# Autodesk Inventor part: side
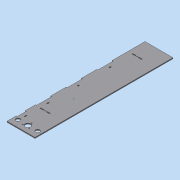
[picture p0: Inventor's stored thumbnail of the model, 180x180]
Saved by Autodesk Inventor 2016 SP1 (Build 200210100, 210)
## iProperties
Created: 2016-06
Part Number: side
Material: Generic
Document SubType Name: Modeling
Designer: Mohamed A.
Density: 1 g/cm^3
Appearance: Default
d0: 85.000 mm
d1: 320.000 mm
d2: 3.000 mm
d3: 0.00 deg
d6: 3.000 mm
d4: 233.000 mm
Author: Mohamed A.
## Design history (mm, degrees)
sketch "Sketch1"
  geometry: L1 (-42.5, 160)-(42.5, 160); L2 (42.5, 160)-(42.5, -160); L3 (42.5, -160)-(-42.5, -160); L4 (-42.5, -160)-(-42.5, 160); L5 (-42.5, 160)-(42.5, -160); L6 (42.5, 160)-(-42.5, -160); 1 further point
  constraints: 12 end point, 2 midpoint, 2 parallel, 1 horizontal, 1 perpendicular
  dimensions: "d0" = 85 distance of L2.end L3.end; "d1" = 320 distance of L1.end L2.end
extrude "Extrusion1" new body sketch "Sketch1" distance "d2" = 3; taper "d3" = 0 deg
sketch "Sketch2"
  geometry: L1 (-26.505, -73)-(-16.505, -73) reference; L2 (-7.505, -76)-(2.495, -76) reference; L3 (42.5, 160)-(-42.5, 160) reference; L4 (-42.5, 113.4)-(-39.5, 113.4); L5 (-39.5, 113.4)-(-39.5, 160); L6 (-42.5, 66.8)-(-39.5, 66.8); L7 (-39.5, 66.8)-(-39.5, 20.2); L8 (-39.5, 20.2)-(-42.5, 20.2); L9 (-39.5, -26.4)-(-42.5, -26.4); L10 (-42.5, -26.4)-(-42.5, -73); L11 (-39.5, 160)-(-42.5, 160); L12 (-42.5, 113.4)-(-42.5, 160); L13 (-42.5, 66.8)-(-42.5, 20.2); L14 (-39.5, -26.4)-(-39.5, -73); L15 (-42.5, -73)-(-39.5, -73); L16 (-42.5, -104)-(-39.5, -104); L17 (-39.5, -104)-(-39.5, -132); L18 (-39.5, -132)-(-42.5, -132); L19 (-42.5, -132)-(-42.5, -104); L20 (-42.5, -160)-(42.5, -160) reference; 1 further point; 1 other entity
  constraints: 32 end point, 6 perpendicular, 5 horizontal, 3 parallel, 2 point on line, 2 vertical, 1 collinear, 2 other
  dimensions: "d4" = 233 distance from line of L3 L1.start (derived); "d6" = 3 distance of L4.start L4.end; "d7" = 46.6 distance between parallel lines of L3 L4 (= 0.2 x d4); "d8" = 3 distance of L6.start L6.end; "d9" = 46.6 distance between parallel lines of L4 L6 (= d7); "d10" = 46.6 distance between parallel lines of L6 L8 (= d7); "d11" = 46.6 distance between parallel lines of L9 L8 (= d10); "d16" = 3 distance of L17.end L18.end; "d17" = 28 distance between parallel lines of L18 L16 (= 0.333333 x d18); "d18" = 84 distance between parallel lines of L20 L2 (derived); "d19" = 28 distance between parallel lines of L16 L2 (= d17); "d20" = 3 distance between parallel lines of L10 L14
extrude "Extrusion2" cut sketch "Sketch2" distance "d12" = 10; taper "d13" = 0 deg
sketch "Sketch3"
  geometry: L1 (-29.5, 142.2)-(-26.5, 142.2); L2 (-26.5, 142.2)-(-26.5, 136.2); L3 (-26.5, 136.2)-(-29.5, 136.2); L4 (-29.5, 136.2)-(-29.5, 142.2); L5 (-29.5, 45.05)-(-26.5, 45.05); L6 (-26.5, 45.05)-(-26.5, 40.5); L7 (-26.5, 40.5)-(-29.5, 40.5); L8 (-29.5, 40.5)-(-29.5, 45.05); L9 (-29.5, -46.7)-(-26.5, -46.7); L10 (-26.5, -46.7)-(-26.5, -52.7); L11 (-26.5, -52.7)-(-29.5, -52.7); L12 (-29.5, -52.7)-(-29.5, -46.7); L13 (-29.5, -115)-(-26.5, -115); L14 (-26.5, -115)-(-26.5, -121); L15 (-26.5, -121)-(-29.5, -121); L16 (-29.5, -121)-(-29.5, -115); L17 (-10.455, 130)-(-13.555, 130) reference; L18 (-10.455, 130)-(-10.455, 127) reference; L19 (-13.555, 127)-(-10.455, 127) reference; L20 (-13.555, 130)-(-13.555, 127) reference; L21 (-10.455, -73)-(-13.555, -73) reference; L22 (-10.455, -73)-(-10.455, -76) reference; L23 (-13.555, -76)-(-10.455, -76) reference; L24 (-13.555, -73)-(-13.555, -76) reference; L25 (-16.505, 130)-(-16.505, 127) reference; L26 (-16.505, 127)-(-26.505, 127) reference; L27 (-26.505, 127)-(-26.505, 130) reference; L28 (-26.505, 130)-(-16.505, 130) reference; L29 (-7.505, 127)-(-7.505, 130) reference; L30 (-7.505, 130)-(2.495, 130) reference; L31 (2.495, 130)-(2.495, 127) reference; L32 (2.495, 127)-(-7.505, 127) reference; L33 (2.495, -73)-(2.495, -76) reference; L34 (2.495, -76)-(-7.505, -76) reference; L35 (-7.505, -76)-(-7.505, -73) reference; L36 (-7.505, -73)-(2.495, -73) reference; L37 (-26.505, -76)-(-26.505, -73) reference; L38 (-26.505, -73)-(-16.505, -73) reference; L39 (-16.505, -73)-(-16.505, -76) reference; L40 (-16.505, -76)-(-26.505, -76) reference; L41 (-21, -118)-(-21, -160) reference; L42 (21, -160)-(21, -118) reference; L43 (-39.5, 160)-(-39.5, 113.4) reference; L44 (-39.5, 160)-(42.5, 160) reference; C1 r 1.4 at (-12.005, 128.5); C2 r 1.4 at (-12.005, -74.5); C3 r 6.3 at (-29.7, -139); C4 r 6.3 at (29.7, -139); C5 r 8.05 at (0, -139) reference; C6 r 8.05 at (0, -139) reference; C7 r 8.5 at (0, -139); C8 r 2 at (0, -127.543) reference; C9 r 2 at (9.922, -144.728) reference; C10 r 2 at (-9.922, -144.728) reference; C11 r 1.4 at (0, -127.543); C12 r 1.4 at (9.922, -144.728); C13 r 1.4 at (-9.922, -144.728); 9 further points
  constraints: 64 end point, 12 horizontal, 8 centre point, 8 parallel, 8 vertical, 4 perpendicular, 3 coincident, 32 other
  dimensions: "d22" = 2.8 diameter of C1; "d23" = 2.8 diameter of C2; "d24" = 12.6 diameter of C3; "d25" = 8.7 distance from line of C3.centre L41; "d26" = 42 distance of L41.start L41.end (derived); "d27" = 21 vertical distance of C3.centre L41.start (= 0.5 x d26); "d28" = 12.6 diameter of C4; "d29" = 21 vertical distance of C4.centre L42.end; "d30" = 8.7 distance from line of L42 C4.centre (= d25); "d32" = 2.8 diameter of C11; "d33" = 2.8 diameter of C12; "d34" = 2.8 diameter of C13; "d35" = 17 diameter of C7; "d38" = 12.99471 distance between parallel lines of L43 L27 (derived); "d39" = 10 distance of L27.end L25.start (derived); "d40" = 9 distance between parallel lines of L25 L29 (derived); "d41" = 10 distance between parallel lines of L29 L31 (derived); "d42" = 30 distance between parallel lines of L44 L28 (derived)
extrude "Extrusion3" cut sketch "Sketch3" distance "d14" = 10; taper "d15" = 0 deg
sketch "Sketch4"
  geometry: 1 further point
sketch "Sketch5"
  geometry: L1 (-82, 3)-(-82, 0) reference; L2 (0, 0)-(-82, 0) reference; L3 (0, 3)-(0, 0) reference; L4 (-82, 3)-(0, 3) reference; L5 (-82, 0)-(-85, 0) reference; L6 (-82, 3)-(-85, 3); L7 (-85, 3)-(-85, 0); L8 (-85, 0)-(-82, 0); L9 (-82, 0)-(-82, 3); 1 further point
  constraints: 8 end point, 2 parallel, 1 horizontal, 1 perpendicular
extrude "Extrusion4" join sketch "Sketch5" distance "d36" = 100; taper "d37" = 0 deg
sketch "Sketch6"
  geometry: L1 (-29.505, 210)-(-19.505, 210); L2 (-19.505, 210)-(-19.505, 207); L3 (-19.505, 207)-(-29.505, 207); L4 (-29.505, 207)-(-29.505, 210); L5 (-10.505, 210)-(-0.505, 210); L6 (-0.505, 210)-(-0.505, 207); L7 (-0.505, 207)-(-10.505, 207); L8 (-10.505, 207)-(-10.505, 210); L9 (-42.5, 160)-(-42.5, 260) reference; L10 (-42.5, 260)-(42.5, 260) reference; L11 (-10.505, 210)-(-19.505, 207); L12 (-10.505, 207)-(-19.505, 210); C1 r 1.4 at (-15.005, 208.5); 1 further point
  constraints: 20 end point, 4 parallel, 2 horizontal, 2 perpendicular, 1 centre point, 1 collinear, 1 midpoint
  dimensions: "d43" = 10 distance of L2.end L3.end; "d44" = 3 distance of L1.end L2.end; "d45" = 10 distance of L6.end L7.end; "d46" = 3 distance of L5.end L6.end; "d47" = 9 distance between parallel lines of L2 L8; "d48" = 12.995 distance between parallel lines of L9 L4; "d49" = 50 distance between parallel lines of L10 L1; "d50" = 2.8 diameter of C1
extrude "Extrusion5" cut sketch "Sketch6" distance "d51" = 100; taper "d52" = 0 deg
body "Solid1"
node "Reference3"
node "Reference4"
node "Reference5"
node "Reference6"
node "Reference7"
node "Reference8"
node "Reference9"
node "Reference10"
node "Reference11"
node "Reference12"
node "Reference13"
node "Projected Loop1"
